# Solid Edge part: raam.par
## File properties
Author: Türk
Template: Iso Part.par
Last saved by: Türk
Revision: 89
Application: Solid Edge
Accuracy: 0,990
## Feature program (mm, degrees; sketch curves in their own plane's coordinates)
thread "unnamed Thread 1"
thread "unnamed Thread 2"
thread "unnamed Thread 3"
thread "unnamed Thread 4"
thread "unnamed Thread 5"
thread "unnamed Thread 6"
thread "unnamed Thread 7"
thread "unnamed Thread 8"
thread "unnamed Thread 9"
thread "unnamed Thread 10"
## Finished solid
Body 1: solid body, 3 faces, 2 edges, 0 vertices.
  Faces by surface: plane 2, spline 1
  Edges by curve: circle 2
Body 2: solid body, 3 faces, 2 edges, 0 vertices.
  Faces by surface: plane 2, spline 1
  Edges by curve: circle 2
Body 3: solid body, 821 faces, 2221 edges, 1304 vertices, 11 internal voids.
  Faces by surface: plane 533, cylinder 201, spline 27, torus 26, swept 25, blend 7, cone 1, sphere 1
  Edges by curve: line 1644, circle 416, intersection 73, spline 45, ellipse 39, curve on surface 4
Bounding box of the edges (mm; curved faces can reach further): 1510.388 x 3740.000 x 1101.094, from (-755.1938, -700, -150) to (755.1938, 3040, 951.0944).
Cylindrical faces by radius (mm): R3 x11, R3.7295 x2, R5 x10, R6.9585 x8, R7.5 x3, R10 x40, R12.5 x6, R15 x6, R20 x31, R25 x54, R40 x7, R50 x5, R60 x2, R70 x1, R80 x1, R100 x2, R225 x4, R240 x4, R250 x4
Conical faces (half-angle, radius in mm at the cone's reference point): 45 deg R80 x1
Toroidal faces (ring radius, tube radius in mm): R30 r50 x1, R50 r7.5 x1, R50 r12.5 x2, R50 r15 x2, R50 r20 x4, R150 r15 x1, R150 r20 x2, R247 r3 x4, R400 r7.5 x1, R400 r12.5 x2, R400 r15 x1, R400 r20 x3, R400 r25 x2
Spherical faces by radius (mm): R3 x1
Planar faces by outward normal: +x 46, +y 74, +z 39, -x 48, -y 65, -z 37, oblique 228
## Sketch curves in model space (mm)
line (-375, 2550, 125) -> (-375, 2501.4617, 125)
arc centre (-425, 2501.4617, 125) radius 50 from (-403.3634, 2456.3855, 125) through (-382.6808, 2474.833, 125) to (-375, 2501.4617, 125)
line (-403.3634, 2456.3855, 125) -> (-596.6366, 2363.6145, 125)
arc centre (-575, 2318.5383, 125) radius 50 from (-625, 2318.5383, 125) through (-617.3192, 2345.167, 125) to (-596.6366, 2363.6145, 125)
line (-625, 2300, 125) -> (-625, 2318.5383, 125)
line (-450, 3240, -89.2893) -> (-439.2893, 3240, -100)
line (-650, 960, 450) -> (-640.4524, 960, 450)
line (-504.2913, 2553.9582, 500.1245) -> (-504.2913, 2570, 500.1245)
line (0, 2770, 150) -> (0, 3400, 150)
line (135, 2850, 150) -> (132.0505, 2850, 150)
line (-425, 0, -125) -> (-425, 25, -125)
line (-425, 25, -125) -> (-455.4523, 144.5251, -125)
line (-455.4523, 144.5251, -125) -> (-476.8912, 228.6728, -125)
line (-476.8912, 228.6728, -125) -> (-612.6174, 761.3983, -125)
arc centre (-225, 860.1543, -125) radius 400 from (-612.6174, 761.3983, -125) through (-617.9824, 785.5564, -125) to (-621.8432, 810, -125)
arc centre (-225, 860.1543, -125) radius 400 from (-621.8432, 810, -125) through (-624.21, 835.0275, -125) to (-625, 860.1543, -125)
line (-625, 860.1543, -125) -> (-625, 960, -125)
line (375, -650, -125) -> (375, -605.372, -125)
arc centre (425, -605.372, -125) radius 50 from (375, -605.372, -125) through (375.2861, -600.0307, -125) to (376.1412, -594.7506, -125)
line (376.1412, -594.7506, -125) -> (415.8705, -411.9955, -125)
arc centre (25, -327.0236, -125) radius 400 from (425, -327.0236, -125) through (422.7111, -369.7541, -125) to (415.8705, -411.9955, -125)
line (425, -220, -125) -> (425, -327.0236, -125)
line (375, -650, -25) -> (375, -642.9764, -25)
line (-749.9141, 2100, 145) -> (-749.9142, 2100, 145)
line (98.7542, 2100, 825) -> (100, 2100, 825)
line (-98.7542, 2100, 825) -> (-100, 2100, 825)
line (749.9141, 2100, 145) -> (749.9142, 2100, 145)
line (-569.1258, 2100, 800.4559) -> (-569.1467, 2100, 800.4559)
line (-569.0201, 2100, 800.4559) -> (-569.1258, 2100, 800.4559)
line (-569.0201, 2100, 800.4559) -> (-569.1467, 2100, 800.4559)
line (569.1259, 2100, 800.4559) -> (569.1468, 2100, 800.4559)
line (569.1259, 2100, 800.4559) -> (569.0197, 2100, 800.4559)
line (569.0197, 2100, 800.4559) -> (569.1468, 2100, 800.4559)
circle centre (400, 1100, 450) radius 40
arc centre (487.8583, 1100, 364.1994) radius 103.0865 from (544.9991, 1100, 450) through (544.8664, 1100, 450.0882) to (544.7336, 1100, 450.1763)
line (-449.9827, 1100, 811.1134) -> (-452.9749, 1100, 810.7809)
line (605, 1100, 150) -> (655, 1100, 150)
arc centre (605, 1100, 145) radius 5 from (605, 1100, 150) through (601.3631, 1100, 148.4312) to (600, 1100, 145)
line (655, 1100, 444.6388) -> (655, 1100, 150)
line (605, 1100, 150) -> (655, 1100, 150)
arc centre (605, 1100, 145) radius 5 from (600, 1100, 145) through (601.5688, 1100, 148.6369) to (605, 1100, 150)
arc centre (749.9141, 1100, 145) radius 5 from (750.0274, 1100, 149.9987) through (753.6329, 1100, 148.3423) to (754.9125, 1100, 144.8721)
line (600, 1100, -150) -> (600, 1100, 145)
line (650, 1100, -150) -> (600, 1100, -150)
spline (650, 1100, -150) -> (732.4046, 1100, -13.8518) -> (754.9125, 1100, 144.8721)
spline (749.905, 1100, 144.6459) -> (729.1623, 1100, -7.1125) -> (655, 1100, -137.721)
line (655, 1100, 144.9822) -> (655, 1100, -137.721)
line (655, 1100, 144.9822) -> (749.905, 1100, 144.6459)
line (449.9827, 1100, 811.1134) -> (452.9749, 1100, 810.7809)
line (449.9827, 1100, 811.1134) -> (452.9749, 1100, 810.7809)
line (591.886, 1100, 731.4928) -> (636.9998, 1100, 550)
arc centre (349.269, 1100, 671.1853) radius 250 from (377.4735, 1100, 919.5892) through (519.499, 1100, 854.2747) to (591.886, 1100, 731.4928)
line (100, 1100, 951.0944) -> (377.4735, 1100, 919.5892)
line (100, 1100, 951.0944) -> (100, 1100, 948.0751)
line (650, 1100, 450) -> (624.7896, 1100, 450)
line (612.3929, 1100, 545.358) -> (624.7896, 1100, 450)
line (567.6243, 1100, 725.462) -> (612.3929, 1100, 545.358)
arc centre (349.269, 1100, 671.1853) radius 225 from (374.6531, 1100, 894.7488) through (502.476, 1100, 835.9658) to (567.6243, 1100, 725.462)
line (97.1616, 1100, 926.256) -> (374.6531, 1100, 894.7488)
line (97.1616, 1100, 926.256) -> (100, 1100, 929.0944)
line (100, 1100, 929.0944) -> (100, 1100, 948.0751)
line (650, 1100, 450) -> (646.9489, 1100, 450.1987)
line (646.9489, 1100, 450.1987) -> (646.9489, 1100, 150)
line (646.9489, 1100, 150) -> (755.0283, 1100, 150)
spline (755.0283, 1100, 150) -> (743.6896, 1100, 321.1393) -> (650, 1100, 450)
line (-624.7896, 1100, 450) -> (-612.3929, 1100, 545.358)
line (-612.3929, 1100, 545.358) -> (-567.6243, 1100, 725.462)
arc centre (-349.269, 1100, 671.1853) radius 225 from (-567.6243, 1100, 725.462) through (-492.6986, 1100, 844.5431) to (-374.6531, 1100, 894.7488)
line (-374.6531, 1100, 894.7488) -> (-97.1616, 1100, 926.256)
line (-100, 1100, 929.0944) -> (-97.1616, 1100, 926.256)
line (-100, 1100, 948.0751) -> (-100, 1100, 929.0944)
line (-100, 1100, 948.0751) -> (-100, 1100, 951.0944)
line (-100, 1100, 951.0944) -> (-377.4735, 1100, 919.5892)
arc centre (-349.269, 1100, 671.1853) radius 250 from (-377.4735, 1100, 919.5892) through (-519.499, 1100, 854.2747) to (-591.886, 1100, 731.4928)
line (-591.886, 1100, 731.4928) -> (-636.9584, 1100, 550.1667)
arc centre (-634.047, 1100, 549.443) radius 3 from (-636.9584, 1100, 550.1667) through (-636.995, 1100, 549.9991) to (-637.0219, 1100, 549.8297)
spline (-646.9489, 1100, 450.1987) -> (-743.8572, 1100, 319.9786) -> (-754.9125, 1100, 144.8721)
arc centre (-749.9141, 1100, 145) radius 5 from (-750.0274, 1100, 149.9987) through (-753.6329, 1100, 148.3423) to (-754.9125, 1100, 144.8721)
spline (-750.0274, 1100, 149.9987) -> (-739.1023, 1100, 317.8977) -> (-655, 1100, 444.6388)
line (-655, 1100, 444.6388) -> (-655, 1100, 150)
line (-605, 1100, 150) -> (-655, 1100, 150)
arc centre (-605, 1100, 145) radius 5 from (-600, 1100, 145) through (-601.5688, 1100, 148.6369) to (-605, 1100, 150)
line (-600, 1100, 145) -> (-600, 1100, 400)
line (-600, 1100, 400) -> (600, 1100, 400)
line (600, 1100, 400) -> (600, 1100, 145)
line (-650, 1100, 450) -> (-646.9489, 1100, 450.1987)
line (-637.0219, 1100, 549.8297) -> (-650, 1100, 450)
line (545, 1100, 450) -> (444.1379, 1100, 516.7221)
arc centre (400, 1100, 450) radius 80 from (377.1429, 1100, 526.6652) through (411.7445, 1100, 529.1332) to (444.1379, 1100, 516.7221)
line (377.1429, 1100, 526.6652) -> (120, 1100, 450)
line (0, 2130.2706, 800.4559) -> (0, 2193.8467, 800.4559)
line (400, 2550, -120) -> (0, 2770, -120)
line (0, 1337.5, -100) -> (0, 1086.4719, -100)
line (149.2291, 270, -100) -> (149.2291, 360, -100)
line (-150.7709, 360, -100) -> (-150.7709, 270, -100)
line (-650, 960, 450) -> (-650, 960, 450.3463)
arc centre (-661.4189, 960, 408.1877) radius 40 from (-671.873, 960, 446.7975) through (-666.692, 960, 447.8386) to (-661.4189, 960, 448.1877)
line (650, 960, 450) -> (650, 960, 450.3463)
arc centre (661.4189, 960, 408.1877) radius 40 from (671.873, 960, 446.7975) through (666.692, 960, 447.8386) to (661.4189, 960, 448.1877)
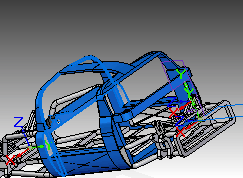
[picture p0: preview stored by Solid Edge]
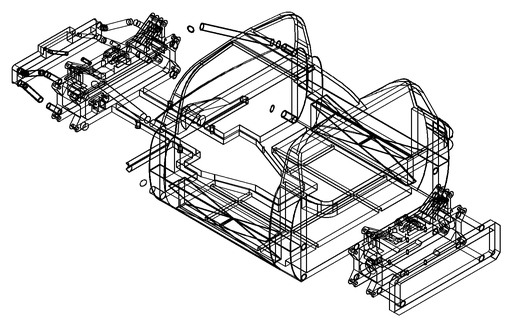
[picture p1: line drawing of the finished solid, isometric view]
